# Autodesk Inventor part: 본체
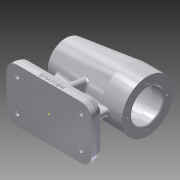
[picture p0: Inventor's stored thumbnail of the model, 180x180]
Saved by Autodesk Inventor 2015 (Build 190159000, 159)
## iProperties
Created: 2017-01
Part Number: 본체
Material: 알루미늄 6061
Document SubType Name: Modeling
Designer: Administrator
Mass: 793.172 g
Surface Area: 661.111 cm^2
Volume: 293.767 cm^3
Density: 2.7 g/cm^3
Appearance: 알루미늄 - 평지
Author: Administrator
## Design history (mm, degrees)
sketch "스케치1"
  geometry: 1 further point
sketch "스케치2"
  geometry: 1 further point
sketch "스케치3"
  geometry: L1 (-56, -35)-(56, -35); L2 (56, -35)-(56, 35); L3 (56, 35)-(-56, 35); L4 (-56, 35)-(-56, -35); L5 (-56, -35)-(56, 35); L6 (56, -35)-(-56, 35); 1 further point
  constraints: 12 end point, 2 midpoint, 2 parallel, 1 horizontal, 1 perpendicular
  dimensions: "d0" = 112 distance of L3.end L2.end; "d1" = 70 distance of L2.end L1.end
extrude "돌출1" new body sketch "스케치3" distance "d2" = 7; taper "d3" = 0 deg
sketch "스케치4"
  geometry: 1 further point
sketch "스케치5"
  geometry: L1 (42, 35)-(-42, 35); L2 (-56, 21)-(-56, -21); L3 (-42, -35)-(42, -35); L4 (56, -21)-(56, 21); L5 (56, 35)-(-56, -35); L6 (-56, 35)-(56, -35); A1 r 14 centre (-42, 21) between (-42, 35) and (-56, 21); A2 r 14 centre (-42, -21) between (-56, -21) and (-42, -35); A3 r 14 centre (42, -21) between (42, -35) and (56, -21); A4 r 14 centre (42, 21) between (56, 21) and (42, 35); 1 further point
  constraints: 12 end point, 8 point on circle, 8 point on line, 8 tangent, 4 centre point, 3 equal radius, 2 midpoint, 2 parallel, 1 horizontal, 1 perpendicular
  dimensions: "d4" = 14 radius of A1
extrude "돌출2" join sketch "스케치5" distance "d5" = 7; taper "d6" = -15 deg
fillet "모깎기1" dims "d7" = 14
sketch "스케치6"
  geometry: L1 (56, 35)-(-56, 35); L2 (-56, 35)-(-56, -35); L3 (-56, -35)-(56, -35); L4 (56, -35)-(56, 35); L5 (56, 35)-(-56, -35); L6 (-56, 35)-(56, -35); C1 r 2.5 at (-42, -21); C2 r 2.5 at (42, -21); C3 r 2.5 at (-42, 21); C4 r 2.5 at (42, 21); 1 further point
  constraints: 12 end point, 4 centre point, 2 horizontal, 2 midpoint, 2 parallel, 1 perpendicular, 1 vertical, 6 other
  dimensions: "d8" = 5 diameter of C1; "d9" = 112 distance of L3.end L2.end; "d10" = 70 distance of L2.end L1.end; "d11" = 42 horizontal distance of point (0, 0) C1.centre; "d12" = 21 vertical distance of point (0, 0) C1.centre; "d15" = 84 distance of C1.centre C2.centre; "d18" = 42 distance of C1.centre C3.centre
extrude "돌출3" cut sketch "스케치6" stored distance "d21" = 7; taper "d22" = 0 deg
sketch "스케치8"
  geometry: L1 (38, -4)-(-38, -4); L2 (-38, -4)-(-38, 4); L3 (-38, 4)-(38, 4); L4 (38, 4)-(38, -4); L5 (38, -4)-(-38, 4); L6 (-38, -4)-(38, 4); L7 (-56, 21)-(-56, -21) reference; 1 further point
  constraints: 12 end point, 2 midpoint, 2 parallel, 1 horizontal, 1 perpendicular
  dimensions: "d34" = 8 distance of L1.end L2.end; "d35" = 18 distance between parallel lines of L7 L2
sketch "스케치9"
  geometry: L1 (56, 108)-(56, 74); L2 (56, 74)-(-56, 74); L3 (56, 108)-(28, 108); L4 (28, 108)-(-52.27, 98.144); L5 (-42, 0)-(42, 0) reference; L6 (56, 0)-(56, 7) reference; A1 r 80 centre (24, 74) between (-52.27, 98.144) and (-56, 74); 1 further point
  constraints: 8 end point, 2 point on circle, 1 centre point, 1 horizontal, 1 perpendicular, 1 point on line, 1 vertical
  dimensions: "d36" = 28 distance of L1.start L3.end; "d37" = 34 distance between parallel lines of L2 L3; "d38" = 74 distance between parallel lines of L5 L2; "d39" = 0 distance from line of L6 L1.end; "d40" = 7 deg angle of L3 L4; "d42" = 112 distance from line of L2.end L1; "d43" = 80 radius of A1
revolve "회전1" sketch "스케치9" stored, may be unused: angle "d44" = 90 deg
extrude "돌출5" join sketch "스케치8" stored distance "d45" = 4; taper "d46" = 0 deg
fillet "모깎기2" dims "d47" = 3
sketch "스케치10"
  geometry: L1 (14, -4)-(40.236, -4) reference; L2 (40.236, -4)-(48.415, -4) reference; L3 (40.236, -4)-(48.415, -4) reference; L4 (48.415, 4)-(40.236, 4) reference; L5 (14, -21)-(14, -33.124) reference; L6 (14, -21)-(14, 21) reference; L7 (59.846, -14.916)-(14, -23); L8 (0, -35)-(7, -35) reference; C1 r 24.382 at (74, 0) reference; A1 r 34 centre (74, 0) between (40.236, -4) and (40.236, 4) reference; A2 r 25.896 centre (74, 0) between (48.415, 4) and (48.415, -4) reference; 1 further point
  constraints: 2 end point, 1 point on line
  dimensions: "d48" = 100 deg angle of L5 L7; "d49" = 12 distance from line of L7.end L8
feature "리브1" sketch "스케치10" dims "d50" = 1, "d51" = 8, "d52" = 0, "d53" = 0, "d54" = 1, "d55" = 1
sketch "스케치11" dims "d56" = 10
  geometry: L1 (46.33, 23.5)-(46.33, 18.5); L2 (46.33, 18.5)-(42, 16); L3 (42, 16)-(37.67, 18.5); L4 (37.67, 18.5)-(37.67, 23.5); L5 (37.67, 23.5)-(42, 26); L6 (42, 26)-(46.33, 23.5); L7 (42, 35)-(-42, 35) reference; L8 (-42, 35)-(-42, 33.124) reference; L9 (-42, 33.124)-(42, 33.124) reference; L10 (42, 35)-(42, 33.124) reference; L11 (54.124, 21)-(54.124, -21) reference; L12 (56, -21)-(54.124, -21) reference; L13 (56, -21)-(56, 21) reference; L14 (56, 21)-(54.124, 21) reference; L15 (-46.33, 18.5)-(-46.33, 23.5); L16 (-46.33, 23.5)-(-42, 26); L17 (-42, 26)-(-37.67, 23.5); L18 (-37.67, 23.5)-(-37.67, 18.5); L19 (-37.67, 18.5)-(-42, 16); L20 (-42, 16)-(-46.33, 18.5); L21 (37.67, -23.5)-(37.67, -18.5); L22 (37.67, -18.5)-(42, -16); L23 (42, -16)-(46.33, -18.5); L24 (46.33, -18.5)-(46.33, -23.5); L25 (46.33, -23.5)-(42, -26); L26 (42, -26)-(37.67, -23.5); L27 (-46.33, -23.5)-(-46.33, -18.5); L28 (-46.33, -18.5)-(-42, -16); L29 (-42, -16)-(-37.67, -18.5); L30 (-37.67, -18.5)-(-37.67, -23.5); L31 (-37.67, -23.5)-(-42, -26); L32 (-42, -26)-(-46.33, -23.5); C1 r 2.5 at (42, 21) reference; 3 further points
  constraints: 48 end point, 2 coincident, 1 horizontal, 1 vertical, 52 other
  dimensions: "d57" = 4.33013 horizontal distance of C1.centre L1.end; "d60" = 84 distance of L3.end L15.start; "d63" = 42 distance of L3.end L21.start
extrude "돌출6" cut sketch "스케치11" distance "d66" = 4; taper "d67" = 0 deg
sketch "스케치12"
  geometry: L1 (-50, 74)-(56, 74); L2 (56, 74)-(56, 95); L3 (56, 95)-(41, 95); L4 (41, 95)-(41, 98); L5 (41, 98)-(-13, 98); L6 (-13, 98)-(-13, 95); L7 (-13, 95)-(-25, 95); L8 (-25, 95)-(-25, 91.5); L9 (-25, 91.5)-(-43, 91.5); L10 (-43, 91.5)-(-43, 90); L11 (-47, 90)-(-43, 90); L12 (56, 7)-(56, 0) reference; L13 (-47, 90)-(-47, 84.5); L14 (-47, 84.5)-(-50, 84.5); L15 (-50.331, 98.382)-(-50.331, 49.618) reference; L16 (-50, 84.5)-(-50, 74); 1 further point
  constraints: 28 end point, 10 perpendicular, 2 point on line, 1 horizontal, 1 vertical
  dimensions: "d68" = 0 distance between parallel lines of L12 L2; "d69" = 74 distance from line of point (0, 0) L1; "d70" = 21 distance between parallel lines of L1 L3; "d71" = 24 distance between parallel lines of L1 L5; "d72" = 15 distance of L2.end L3.end; "d73" = 54 distance of L4.end L5.end; "d74" = 12 distance of L6.end L7.end; "d75" = 17.5 distance between parallel lines of L1 L9; "d76" = 18 distance of L8.end L9.end; "d77" = 4 distance of L11.start L10.end; "d78" = 16 distance between parallel lines of L1 L11; "d79" = 3 distance of L13.end L14.end; "d80" = 10.5 distance between parallel lines of L1 L14
revolve "회전2" sketch "스케치12" stored, may be unused: angle "d81" = 90 deg
fillet "모깎기3" dims "d82" = 3
fillet "모깎기4" dims "d83" = 0.3
fillet "모깎기5" dims "d84" = 3
chamfer "모따기1" distance "d85" = 1; stored, may be unused: second distance "d86" = 2, angle "d87" = 45 deg
fillet "모깎기6" dims "d88" = 3
fillet "모깎기7" dims "d89" = 3
fillet "모깎기8" dims "d90" = 3
fillet "모깎기9" dims "d91" = 3
sketch "스케치13" dims "d94" = 52
  geometry: L1 (-21, -74)-(21, -74) reference; 5 further points
  constraints: 4 vertical alignment, 2 midpoint, 2 other
  dimensions: "d93" = 74 distance of point (0, -74) point (0, 0)
hole "구멍1" sketch "스케치13" at (0, 26) diameter "d95" = 3.242; stored, may be unused: countersink angle "d99" = 90 deg, drill point angle "d101" = 118 deg; dims "d96" = 8, "d97" = 4, "d98" = 2, "d100" = 11
node "작업 평면2"
sketch "스케치14"
  geometry: L1 (56, 0)-(42, 0) reference; L2 (56, 0)-(56, 7) reference; 2 further points
  constraints: 1 other
  dimensions: "d108" = 56 horizontal distance of L1.start point (0, 4); "d109" = 4 vertical distance of L1.start point (0, 4)
feature "엠보싱1" sketch "스케치14" dims "d110" = 0.5, "d111" = 0
fillet "모깎기10" dims "d112" = 1
fillet "모깎기11" dims "d113" = 3
node "솔리드1"
mirror "대칭1"
pattern_circular "원형 패턴1" dims angle "d103" = 360 deg
node "투영된 루프1"
node "작업 평면1"
node "투영된 루프2"
node "투영된 루프3"
